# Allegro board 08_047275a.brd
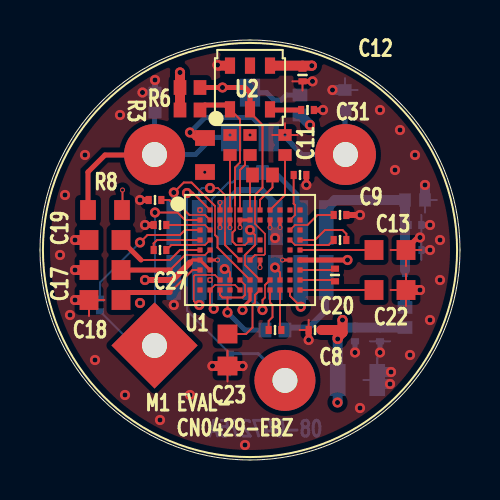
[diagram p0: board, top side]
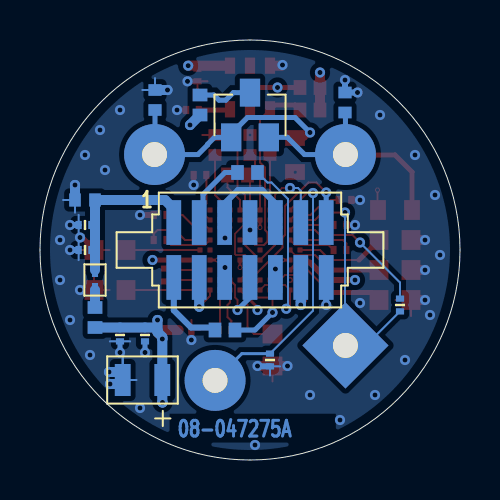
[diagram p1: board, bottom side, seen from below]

Outline 21 x 21 mm; copper layers: TOP, LAYER2, LAYER3, BOTTOM. Coordinates in mm from the lower left corner of the outline.
Outline path: 0,10.5 arc(3.08,17.92) 10.5,21 arc(17.92,17.92) 21,10.5 arc(17.92,3.08) 10.5,0 arc(3.08,3.08) 0,10.5

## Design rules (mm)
constraint set DEFAULT: min track width 0.1

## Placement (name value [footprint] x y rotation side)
C1  0.1uF  [C0201]  3 7.75 270 bottom
C2  0.1uF  [C0201]  9.5 5 270 bottom
C3  30PF  [C0402]  15.25 18 90 bottom
C4  30PF  [C0402]  5.75 17.88 270 bottom
C6  4.7uF  [C0402]  9.5 15.75 270 top
C7  4.7uF  [CPL0805]  15.88 4 0 bottom
C8  0.1uF  [C0201]  13.75 6.5 0 top
C9  0.1uF  [C0201]  15 12.25 180 top
C10  0.1uF  [C0201]  13 14.25 180 top
C11  4.7uF  [C0402]  12.25 15.75 270 top
C12  0.1uF  [C0201]  13.12 19.25 90 top
C13  0.47uF  [C0603]  17.5 10.5 0 top
C14  4.7uF  [C0402]  10.5 15.75 270 top
C15  0.1uF  [C0201]  6 11.75 0 top
C16  0.1uF  [C0201]  5.75 13 0 top
C17  0.47uF  [C0603]  3.25 9.5 180 top
C18  0.47uF  [C0603]  3.25 8 180 top
C19  0.47uF  [C0603]  3.25 11 180 top
C20  0.1uF  [C0201]  14.75 9.25 270 top
C21  0.1uF  [C0201]  11.75 6.5 180 top
C22  0.47uF  [C0603]  17.5 8.5 180 top
C23  0.47uF  [C0603]  9.38 5.5 90 top
C24  4.7UF  [C0402]  18.75 13 0 bottom
C25  0.1uF  [C0201]  18.75 11.75 0 bottom
C26  0.1uF  [C0201]  15.75 6.25 90 bottom
C27  0.1uF  [C0201]  6 10.5 180 top
C28  0.1uF  [C0201]  15 11 0 top
C29  1000PF  [C0201]  18.75 10.5 180 bottom
C30  1000PF  [C0201]  17 6.25 90 bottom
C31  0.1uF  [C0201]  13.38 17.5 180 top
E2  600OHM AT 100MEGHZ  [L0201H13]  18.25 9 270 bottom
M1  CO-A4  [MCO-A4_SKTLD98]  10.5 10.5 45 top
NOREF  -  []  5.75 6 0 top
NOREF#2  -  []  -124.5 -119.5 0 top
NOREF#3  -  []  5.5 15.5 0 top
NOREF#4  -  []  15.25 15.75 0 top
NOREF#5  -  []  -124.5 -119.5 0 top
NOREF#6  -  []  7.67 14.62 0 top
NOREF#7  -  []  9.75 -12.75 0 top
NOREF#8  -  []  18.18 3.34 0 top
NOREF#9  -  []  12.5 4 0 top
P1  SFM-107-02-L-D  [CNSAMTECSFM-107-02-X-D]  10.5 10.5 180 bottom
Q1  MMBFJ177  [SOT23]  10.5 17.25 180 bottom
R1  100  [R0402]  10.62 14.38 0 bottom
R2  100  [R0402]  11.75 6.5 180 bottom
R3  2.2K  [R0402]  7.5 17.5 0 top
R4  200  [R0402]  11.12 14.25 180 top
R5  100K  [R0402]  13 17.75 90 bottom
R6  2.2K  [R0402]  7.5 18.62 0 top
R7  0  [R0603]  8.25 15.25 270 top
R8  0  [R0603]  3.25 12.5 0 top
R11  1.6  [R0402]  18.25 7.12 270 bottom
U1  ADUCM355  [LGA72_5X6]  10.5 10.5 270 top
U2  MVH3002D  [LGA6H35]  10.5 18.62 0 top

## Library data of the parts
C1 C2 C8-C10 C12 C15 C16 C20 C21 C25-C28 C31 = CAP: Tolerance: 10; User Part Number: UPN; alternate symbols: (); part number: CAP_SM-0.1UF,6.3V,10,E011567,C0201; tolerance: 10
C3 C4 = CAP: User Part Number: UPN; Tolerance: 1; alternate symbols: (); part number: CAP_SM-30PF,50V,1,E023309,C0402; tolerance: 1
C6 C11 C14 = CAP: User Part Number: UPN; Tolerance: 10; alternate symbols: (); part number: CAP_SM-4.7UF,6.3V,10,E020089,C0402; tolerance: 10
C7 = CAPP: Tolerance: N/A; User Part Number: UPN; alternate symbols: (); part number: CAPP_SM-4.7UF,N/A,N/A,E020900,CPL0805; tolerance: N/A
C13 C17-C19 C22 C23 = CAP: User Part Number: UPN; Tolerance: 10; alternate symbols: (); part number: CAP_SM-0.47UF,25V,10,E010966,C0603; tolerance: 10
C24 = CAP: User Part Number: UPN; Tolerance: 20; alternate symbols: (); part number: CAP_SM-4.7UF,6.3V,20,E025260,C0402; tolerance: 20
C29 C30 = CAP: Tolerance: 5; User Part Number: UPN; alternate symbols: (); part number: CAP_SM-1000PF,25V,5,E028646,C0201; tolerance: 5
E2 = FERRITE: Tolerance: 25; User Part Number: UPN; alternate symbols: (); part number: FERRITE_SM-600OHM AT 100MEGHZ,25,E024592,L0201H13; tolerance: 25
M1 = MOD_CO_XX_V2: User Part Number: UPN; Tolerance: N/A; alternate symbols: (); part number: MOD_CO_XX_V2_TH-CO-A4,E025025,MCO-A4_SKTLD98; tolerance: N/A
P1 = CN14P_ODD_EVEN: User Part Number: UPN; Tolerance: N/A; alternate symbols: (); part number: CN14P_ODD_EVEN_SM-SFM-107-02-L-D,E029706,CNSAMTECSFM-107-02-X-D; tolerance: N/A
Q1 = TRANPJFET: User Part Number: UPN; Tolerance: N/A; alternate symbols: (); part number: TRANPJFET_SM-MMBFJ177,E020441,SOT23; tolerance: N/A
R1 R2 = RES: User Part Number: UPN; Tolerance: 1; alternate symbols: (R0402L); part number: RES_SM-100,E016329,1/10W,1,R0402; tolerance: 1
R3 R6 = RES: User Part Number: UPN; Tolerance: 5; alternate symbols: (R0402L); part number: RES_SM-2.2K,E003446,1/16W,5,R0402; tolerance: 5
R4 = RES: User Part Number: UPN; Tolerance: 0.1; alternate symbols: (R0402L); part number: RES_SM-200,E006431,1/16W,0.1,R0402; tolerance: 0.1
R5 = RES: User Part Number: UPN; Tolerance: 1; alternate symbols: (R0402L); part number: RES_SM-100K,E017051,1/16W,1,R0402; tolerance: 1
R7 R8 = RES: User Part Number: UPN; Tolerance: 5; alternate symbols: (R0603L); part number: RES_SM-0,E006826,1/10W,5,R0603; tolerance: 5
R11 = RES: User Part Number: UPN; Tolerance: 1; alternate symbols: (R0402L); part number: RES_SM-1.6,E014755,1/16W,1,R0402; tolerance: 1
U1 = ADUCM355: User Part Number: UPN; Tolerance: N/A; alternate symbols: (SKTPLA-72LHC50A01); part number: ADUCM355_SM-ADUCM355,E028185,LGA72_5X6; tolerance: N/A
U2 = ICMVH300XD: User Part Number: UPN; Tolerance: N/A; alternate symbols: (); part number: ICMVH300XD_SM-MVH3002D,E029189,LGA6H35; tolerance: N/A

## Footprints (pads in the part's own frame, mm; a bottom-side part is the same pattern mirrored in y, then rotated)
C0201
  rect 0.305x0.406 smd: 1(-0.318,0) 2(0.318,0)
C0402
  rect 0.584x0.66 smd: 1(-0.5,0) 2(0.5,0)
C0603
  rect 0.94x0.991 smd: 1(-0.8,0) 2(0.8,0)
CNSAMTECSFM-107-02-X-D
  rect 0.737x2.235 smd: 1(-3.81,1.372) 2(-3.81,-1.372) 3(-2.54,1.372) 4(-2.54,-1.372) 5(-1.27,1.372) 6(-1.27,-1.372) 7(0,1.372) 8(0,-1.372) 9(1.27,1.372) 10(1.27,-1.372) 11(2.54,1.372) 12(2.54,-1.372) 13(3.81,1.372) 14(3.81,-1.372)
CPL0805
  rect 0.787x1.6 smd: N(0.991,0) P(-0.991,0)
L0201H13
  rect 0.254x0.305 smd: 1(-0.277,0) 2(0.277,0)
LGA6H35
  rect 0.508x0.813 smd: 1(-1,-1.091) 2(0,-1.091) 3(1,-1.091) 4(1,1.091) 5(0,1.091) 6(-1,1.091)
LGA72_5X6
  rect 0.254x0.254 smd: A1(-2,-2.5) A2(-2,-2) A3(-2,-1.5) A4(-2,-1) A5(-2,-0.5) A6(-2,0) A7(-2,0.5) A8(-2,1) A9(-2,1.5) A10(-2,2) A11(-2,2.5) B1(-1.5,-2.5) B2(-1.5,-2) B3(-1.5,-1.5) B4(-1.5,-1) B5(-1.5,-0.5) B6(-1.5,0) B7(-1.5,0.5) B8(-1.5,1) B9(-1.5,1.5) B10(-1.5,2) B11(-1.5,2.5) C1(-1,-2.5) C2(-1,-2) C10(-1,2) C11(-1,2.5) D1(-0.5,-2.5) D2(-0.5,-2) D5(-0.5,-0.5) D6(-0.5,0) D7(-0.5,0.5) D10(-0.5,2) D11(-0.5,2.5) E1(0,-2.5) E2(0,-2) E5(0,-0.5) E7(0,0.5) E10(0,2) E11(0,2.5) F1(0.5,-2.5) F2(0.5,-2) F5(0.5,-0.5) F6(0.5,0) F7(0.5,0.5) F10(0.5,2) F11(0.5,2.5) G1(1,-2.5) G2(1,-2) G10(1,2) G11(1,2.5) H1(1.5,-2.5) H2(1.5,-2) H3(1.5,-1.5) H4(1.5,-1) H5(1.5,-0.5) H6(1.5,0) H7(1.5,0.5) H8(1.5,1) H9(1.5,1.5) H10(1.5,2) H11(1.5,2.5) J1(2,-2.5) J2(2,-2) J3(2,-1.5) J4(2,-1) J5(2,-0.5) J6(2,0) J7(2,0.5) J8(2,1) J9(2,1.5) J10(2,2) J11(2,2.5)
MCO-A4_SKTLD98
  rect 3.048x3.048 hole 1.25: 1(-6.75,0)
  round 3.048 hole 1.25: 2(0,6.75) 3(6.75,0) 4(-3.375,-5.846)
R0402
  rect 0.635x0.737 smd: 1(-0.5,0) 2(0.5,0)
R0603
  rect 0.787x0.991 smd: 1(-0.85,0) 2(0.85,0)
SOT23
  rect 1.016x1.397 smd: 1(-0.94,-1.118) 2(0.94,-1.118) 3(0,1.118)

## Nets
DGND: C2.2(N2) C3.2(N2) C4.1 C6.1 C7.N(N2) C8.1 C9.1 C10.1 C11.1 C12.1 C13.2(N2) C14.1 C15.1 C16.1 C17.2(N2) C18.2(N2) C19.2(N2) C22.1 C23.1 C24.2(N2) C25.2(N2) C26.1 C29.1 C30.1 C31.1 P1.5 P1.9 P1.14(N7) U1.B3 U1.B4 U1.B5 U1.B6 U1.B8 U1.B9 U1.F2 U1.F7 U1.F10 U1.H2 U2.6(VSS)
VBAT: C24.1 C25.1 C29.2(N2) E2.1 P1.1
VDD: C7.P C8.2(N2) C12.2(N2) C26.2(N2) C30.2(N2) R3.1 R5.1 R6.1 R11.2(N2) U1.F1 U1.F11 U1.G2 U1.J6 U2.4
BB_SCL/CS0: R3.2(N2) U1.D6 U2.1
BB_SDA/MISO: R6.2(N2) U1.F6 U2.2
CAP_POT0: C1.1 U1.C1
CE0: C1.2(N2) M1.1 U1.B1
DE0: C2.1 M1.4 U1.A2
EXT_INT: P1.11 U1.F5
LPF0: C6.2(N2) U1.A4
LPF1: C11.2(N2) U1.A8
RC0_0: C27.2(N2) U1.D1
RC0_1: C27.1 U1.D2
RC1_0: C28.2(N2) U1.D11
RC1_1: C28.1 U1.D10
RE0: C3.1 M1.3 Q1.1 R7.1
RESET: P1.4 U1.J10
SCL/UART_RX: R1.1 U1.J2 U1.J5
SDA/UART_TX: R2.2(N2) U1.H5 U1.J3
SE0: C4.2(N2) M1.2(WE) Q1.2(S) R8.1
SPI0_CLK: P1.6 U1.H9
SPI0_CS0: P1.13 U1.H6
SPI0_MISO: P1.7 U1.H7
SPI0_MOSI: P1.8 U1.H8
SWCLK: P1.12 U1.H3
SWDIO: P1.10 U1.H4
UNNAMED_4_ADUCM355_I48_ADCVBIAS: C13.1 U1.E11
UNNAMED_4_ADUCM355_I48_AVDDREG: C19.1 U1.E1
UNNAMED_4_ADUCM355_I48_DVDDREG: C23.2(N2) U1.J7
UNNAMED_4_ADUCM355_I48_DVDDREGA: C18.1 U1.G1
UNNAMED_4_ADUCM355_I48_RCAL0: R4.1 U1.A7
UNNAMED_4_ADUCM355_I48_RCAL1: R4.2(N2) U1.A6
UNNAMED_4_ADUCM355_I48_RE0: R7.2(N2) U1.A1
UNNAMED_4_ADUCM355_I48_SE0: R8.2(N2) U1.A3
UNNAMED_4_ADUCM355_I48_VBIAS0: C15.2(N2) U1.C2
UNNAMED_4_ADUCM355_I48_VBIAS1: C9.2(N2) U1.C10
UNNAMED_4_ADUCM355_I48_VCDCCAP2: C20.1 U1.G11
UNNAMED_4_ADUCM355_I48_VDCDCC_1: C21.1 U1.J9
UNNAMED_4_ADUCM355_I48_VDCDCC_2: C20.2(N2) U1.H11
UNNAMED_4_ADUCM355_I48_VDCDCC_3: C22.2(N2) U1.J11
UNNAMED_4_ADUCM355_I48_VDCDCCAP: C21.2(N2) U1.J8
UNNAMED_4_ADUCM355_I48_VREF1: C14.2(N2) U1.A5
UNNAMED_4_ADUCM355_I48_VREF2: C17.1 U1.E2
UNNAMED_4_ADUCM355_I48_VZERO0: C16.2(N2) U1.B2
UNNAMED_4_ADUCM355_I48_VZERO1: C10.2(N2) U1.B10
UNNAMED_4_CAP_I187_N2: C31.2(N2) U2.3
UNNAMED_4_CN14PODDEVEN_I182_N2: P1.3 R1.2(N2)
UNNAMED_4_CN14PODDEVEN_I199_N1: P1.2 R2.1
UNNAMED_4_FERRITE_I82_N2: E2.2(N2) R11.1
UNNAMED_4_RES_I195_N2: Q1.3 R5.2(N2)

Pads without a net: U1 A9 A10 A11 B7 B11 C11 D5 D7 E5 E7 E10 G10 H1 H10 J1 J4; U2 5

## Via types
v1: diameter 0.254, hole 0.152, TOP to LAYER2, 16 vias
v2: diameter 0.508, hole 0.254, TOP to BOTTOM, 71 vias

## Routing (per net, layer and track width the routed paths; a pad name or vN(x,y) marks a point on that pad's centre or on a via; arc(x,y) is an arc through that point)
DGND: length 49.2
  TOP w0.1: 11.62,16.25 v1(12.25,16.25) ; v1(12.25,16.25) 12.88,16.25 ; v1(12.25,16.25) 12.25,16.84 ; C13.2 19.07,10.5 ; C13.2 17.53,10.5 ; C13.2 18.3,9.7 ; 2.45,7.2 C18.2 3.22,8 ; 9.38,5.47 C23.1 9.38,3.93 ; 13.12,18.48 C12.1 12.62,18.93 ; 12.98,6.5 C8.1 13.43,7 ; C22.1 18.3,9.3 ; C22.1 17.53,8.5 ; C22.1 18.3,7.7
  TOP w0.15: U1.F10 v1(12.12,10) ; v1(10,11.62) 10,11.95 10.05,12 ; U1.B8 v1(11.5,11.62) ; U1.B3 v1(9,11.62) ; U1.F7 v1(11,9.62) ; 10.05,12 U1.B6 ; 10.05,12 U1.B5 ; U1.B4 v1(9.5,11.62) ; U1.B9 v1(12,11.62) ; U1.F2 v1(8.88,10)
  TOP w0.25: C12.1 v2(13.62,18.93) ; C13.2 18.3,10.55 18.88,11.12 v2(19,11.12) ; C31.1 v2(14.15,17.5) ; v2(13.32,13.75) C10.1
  TOP w0.3: C9.1 v2(16,12.25) ; C16.1 v2(5,13) ; C8.1 v2(13.43,6) ; C15.1 v2(5.25,11.75)
  TOP w0.5: v2(8.88,19.75) 8.91,19.72 U2.6 ; v2(10.12,4.7) C23.1 v2(8.62,4.7) ; C18.2 v2(1.75,8) ; C22.1 v2(19,8.5) ; C17.2 v2(1.75,9.5) ; C19.2 v2(1.75,11)
  BOTTOM w0.1: 9.5,4.23 C2.2 9,4.68 ; 16.86,4.4 16.86,5.09 16.87,5.1 C7.N ; 19.25,12.37 C24.2 19.84,13 ; C7.N 17.56,4 ; C7.N 16.17,4 ; 16.5,5.93 C30.1 17.5,5.93 ; 15.88,18.5 C3.2 15.25,19.09 ; 19.07,12.25 C25.2 19.07,11.25 ; 19.07,10 C29.1 19.07,11
  BOTTOM w0.25: C26.1 v2(15.75,5.38) ; C30.1 v2(17,5.38)
  BOTTOM w0.3: C2.2 10.11,4.68 v2(10.12,4.7) ; P1.9 9.23,12.83 9.9,13.5 11.1,13.5 11.75,12.85 v2(11.75,11.1) 11.77,11.12 P1.5 ; C25.2 v2(19.5,11.75) ; P1.14 v2(6.69,7.75) ; v2(5.75,19) C4.1 v2(5.12,18.38) ; C29.1 v2(19.5,10.5)
  BOTTOM w0.5: C24.2 v2(19.25,13.75) ; v2(17.55,4.4) 16.86,4.4 16.86,4.01 C7.N 16.87,3.85 16.92,3.8 v2(17.5,3.8) ; C3.2 v2(14.62,18.5)
  vias: v1(8.5,9) v1(9.5,16.25) v1(10.5,16.25) v2(1,10.25) v2(1.25,13.25) v2(1.5,7.25) v2(2.25,15.25) v2(2.75,5) v2(4,17.25) v2(4.25,3.25) v2(5,7.85) v2(6,2) v2(7.5,3.25) v2(10.25,0.75) v2(16,2.6) v2(17,17.5) v2(17.75,14.5) v2(18,16.5) v2(18.5,5.25) v2(18.75,15.25) v2(19.5,7) v2(20,11) v2(20,9)
VBAT: length 8.9
  BOTTOM w0.25: 18.25,9.5 18.25,9.28 ; C25.1 18.25,11.75 ; C29.2 18.25,10.5
  BOTTOM w0.5: 18.25,9.5 C24.1 14.75,13 14.31,12.56 P1.1
VDD: length 21.9
  TOP w0.15: U1.J6 10.5,8 10.12,7.62 v2(10.12,7.5) ; 7.5,9.88 7.62,10 U1.F1 U1.G2
  TOP w0.25: C12.2 13.12,19.72 ; U1.F11 v2(15.38,10)
  TOP w0.3: v2(5.25,9) 6.62,9 7.5,9.88
  TOP w0.5: 15.12,6.38 15,6.5 C8.2 ; 15.12,6.38 14.88,6.13 v2(14.88,6.05) ; 15.12,6.38 v2(15.12,7) ; v2(13.59,19.72) U2.4 ; v2(7,19.38) R6.1 R3.1
  BOTTOM w0.25: 15.75,6.62 C26.2 ; C30.2 17,6.62
  BOTTOM w0.5: R11.2 15.25,6.62 15.12,6.5 ; 15.12,6.5 v2(15.12,7) ; 15.12,6.5 15.12,6.39 14.88,6.15 v2(14.88,6.05) C7.P 14.88,2.88 v2(14.88,2.88) ; R5.1 v2(13.5,16.75)
BB_SCL/CS0: length 9.7
  TOP w0.08: U1.D6 10.25,10.75 9.8,10.75 ; 9.75,11.5 9.75,12.75
  TOP w0.1: U2.1 10,17.03 10,14.88 9.75,14.62 9.75,12.75 ; 9.8,10.75 9.62,10.93 9.62,11.38 9.75,11.5
  TOP w0.25: U2.1 9.28,17.75 8.25,17.75 R3.2
BB_SDA/MISO: length 12.2
  TOP w0.08: 10.75,10.25 11.2,10.25 11.25,10.3 11.25,11.31 10.75,11.81 10.75,12.75
  TOP w0.1: U2.2 10.5,17.38 11.12,16.75 11.12,13.62 10.75,13.25 10.75,12.75 ; U1.F6 10.75,10.25
  TOP w0.25: U2.2 10.5,18.38 10.25,18.62 v2(9.12,18.62) R6.2
CAP_POT0: length 6.9
  TOP w0.1: v2(5,10.88) 5.38,11.25 7,11.25 7.25,11.5 U1.C1
  BOTTOM w0.1: v2(5,10.88) 3,8.88 C1.1
CE0: length 12.5
  TOP w0.1: v2(5.75,12.38) 6.88,12.38 7.25,12 U1.B1
  BOTTOM w0.1: v2(5.75,12.38) 5.75,5.75 M1.1 4.71,5.73 C1.2
DE0: length 13.7
  TOP w0.1: v2(7.35,13.35) 7.38,13.38 7.62,13.38 U1.A2
  BOTTOM w0.1: v2(7.35,13.35) 7.35,7.47 C2.1
  BOTTOM w0.15: C2.1 10.91,5.32 12.25,3.98
EXT_INT: length 6.6
  TOP w0.08: v2(8.5,13.6) 8.9,13.6 9.25,13.25 9.25,11.38
  TOP w0.1: U1.F5 9.25,10.75 9.25,11.38
  BOTTOM w0.1: v2(8.5,13.6) 8.1,13.6 7.96,13.46 P1.11
LPF0: length 2.8
  TOP w0.1: U1.A4 C6.2
LPF1: length 3.1
  TOP w0.1: U1.A8 12.25,13.25 C11.2
RC0_0: length 2.7
  TOP w0.1: U1.D1 5.85,11 5.68,10.83 C27.2
RC0_1: length 2.4
  TOP w0.08: U1.D2 8.25,10.75 7.75,10.75
  TOP w0.1: 7.75,10.75 6.57,10.75 C27.1
RC1_0: length 2.9
  TOP w0.1: C28.2 15.32,11.31 15.12,11.5 14.25,11.5 13.75,11 U1.D11
RC1_1: length 2.4
  TOP w0.08: U1.D10 12.75,10.75 13.38,10.75
  TOP w0.1: 13.38,10.75 14.43,10.75 C28.1
RE0: length 12.1
  TOP w0.25: R7.1 7.78,16.1 v2(7.5,16.38)
  BOTTOM w0.25: v2(7.5,16.38) 8.25,17.12 10.62,17.12 11.44,16.31 Q1.1 12.27,16.13 12.62,15.79 12.62,15.76 13.1,15.27 M1.3 15.25,15.3 C3.1
RESET: length 2.5
  TOP w0.1: U1.J10 12.5,8.21 v2(13.04,7.67)
  BOTTOM w0.5: P1.4 v2(13.04,7.67)
SCL/UART_RX: length 10.3
  TOP w0.08: U1.J5 9.75,8.75 8.75,8.75 U1.J2
  TOP w0.1: v2(8.69,7.56) 8.5,7.75 U1.J2
  BOTTOM w0.1: v2(8.69,7.56) 8.6,7.65 8.6,13.05 9.43,13.88 9.62,13.88 R1.1
SDA/UART_TX: length 5.4
  TOP w0.08: U1.H5 10.25,8.75 10.25,8.25
  TOP w0.1: 9.38,8.12 9.12,8.12 9,8.25 U1.J3 ; 9.38,8.12 10.12,8.12 10.25,8.25 ; 9.38,8.12 v2(9.38,7.38)
  BOTTOM w0.25: R2.2 10.25,6.5 v2(9.38,7.38)
SE0: length 11.9
  TOP w0.25: R8.1 2.4,14.4 3.25,15.25 5.7,15.25 M1.2
  BOTTOM w0.25: C4.2 5.73,17.35 M1.2 7.77,15.27 8.63,16.13 Q1.2
SPI0_CLK: length 0.7
  TOP w0.1: U1.H9 12,9.38 v2(11.75,9.62)
SPI0_CS0: length 8.7
  TOP w0.08: 8.75,12.7 8.75,11.25
  TOP w0.1: U1.H6 8.88,10.62 8.88,11.12 8.75,11.25 ; v2(6.69,13.38) 7.19,13.88 7.58,13.88 8.75,12.7
  BOTTOM w0.25: v2(6.69,13.38) P1.13
SPI0_MISO: length 3.5
  TOP w0.08: 10.25,9.75 10.25,10.25 ; 10.75,10.75 10.75,11.25
  TOP w0.1: U1.H7 10.25,9.75 ; 10.25,10.25 10.75,10.75 ; 10.75,11.25 v2(10.5,11.5)
  BOTTOM w0.1: P1.7 v2(10.5,11.5)
SPI0_MOSI: length 3.5
  TOP w0.08: 11.25,8.75 11.25,8.12
  TOP w0.1: v2(11.12,7.5) 11.12,8 11.25,8.12 ; U1.H8 11.25,8.75
  BOTTOM w0.25: v2(11.12,7.5) 10.5,8.12 P1.8
SWCLK: length 4.4
  TOP w0.08: v2(7.96,7.75) 7.88,7.75 7.69,7.94 7.69,9.19 7.75,9.25 8.75,9.25 U1.H3
  BOTTOM w0.5: P1.12 7.96,7.92 7.96,7.91 v2(7.96,7.75)
SWDIO: length 1.2
  TOP w0.1: v2(9.23,9.55) 9.23,9.5 9.28,9.45 9.43,9.45 9.5,9.38 U1.H4
  BOTTOM w0.25: v2(9.23,9.55) P1.10
UNNAMED_4_ADUCM355_I48_ADCVBIAS: length 3.7
  TOP w0.1: U1.E11 C13.1
UNNAMED_4_ADUCM355_I48_AVDDREG: length 4.6
  TOP w0.1: 5.05,10 6.5,10 7,10.5 U1.E1
  TOP w0.25: C19.1 5.05,10
UNNAMED_4_ADUCM355_I48_DVDDREG: length 3.4
  TOP w0.1: U1.J7 10.75,8.25 10.75,7.88 10.62,7.75 10.62,6.62 10.3,6.3 C23.2
UNNAMED_4_ADUCM355_I48_DVDDREGA: length 4.6
  TOP w0.1: U1.G1 7.62,9.5 6.5,8.38
  TOP w0.25: C18.1 4.42,8.38 6.5,8.38
UNNAMED_4_ADUCM355_I48_RCAL0: length 2
  TOP w0.1: U1.A7 11,13.01 11.62,13.63 R4.1
UNNAMED_4_ADUCM355_I48_RCAL1: length 1.8
  TOP w0.1: U1.A6 10.5,14.12 R4.2
UNNAMED_4_ADUCM355_I48_RE0: length 2
  TOP w0.3: R7.2 v1(8.24,14.39)
  LAYER2 w0.1: v1(8,12.5) 8,14.15 v1(8.24,14.39)
UNNAMED_4_ADUCM355_I48_SE0: length 7.1
  TOP w0.1: R8.2 4.12,12.53 v1(4.12,13.5) ; U1.A3 v1(9,12.88)
  LAYER2 w0.1: v1(4.12,13.5) 5.75,13.5 7.12,12.12 8.25,12.12 v1(9,12.88)
UNNAMED_4_ADUCM355_I48_VBIAS0: length 2.3
  TOP w0.08: U1.C2 8.25,11.75 7.75,11.75
  TOP w0.1: C15.2 7.75,11.75
UNNAMED_4_ADUCM355_I48_VBIAS1: length 2.5
  TOP w0.08: 13.38,11.75 12.75,11.75 U1.C10
  TOP w0.1: C9.2 13.88,12.25 13.38,11.75
UNNAMED_4_ADUCM355_I48_VCDCCAP2: length 1.8
  TOP w0.1: U1.G11 14.68,9.5 C20.1
UNNAMED_4_ADUCM355_I48_VDCDCC_1: length 2
  TOP w0.1: U1.J9 12,6.57 C21.1
UNNAMED_4_ADUCM355_I48_VDCDCC_2: length 1.8
  TOP w0.1: U1.H11 14.68,9 C20.2
UNNAMED_4_ADUCM355_I48_VDCDCC_3: length 3.7
  TOP w0.1: U1.J11 C22.2
UNNAMED_4_ADUCM355_I48_VDCDCCAP: length 2.1
  TOP w0.1: C21.2 11.43,6.95 11.62,7.15 11.62,7.75 11.5,7.88 U1.J8
UNNAMED_4_ADUCM355_I48_VREF1: length 3.1
  TOP w0.1: C14.2 10.3,15.25 10.25,15.2 10.25,14.75 10,14.5 U1.A5
UNNAMED_4_ADUCM355_I48_VREF2: length 4.9
  TOP w0.08: U1.E2 8.25,10.25 7.25,10.25
  TOP w0.1: 6.5,9.5 7.25,10.25
  TOP w0.25: C17.1 6.5,9.5
UNNAMED_4_ADUCM355_I48_VZERO0: length 2.8
  TOP w0.08: 7.47,12.25 8.25,12.25
  TOP w0.1: C16.2 6.47,13 6.82,12.65 7.07,12.65 7.47,12.25 ; 8.25,12.25 U1.B2
UNNAMED_4_ADUCM355_I48_VZERO1: length 2.4
  TOP w0.08: U1.B10 12.75,12.25 12.75,12.75
  TOP w0.1: C10.2 12.68,12.82 12.75,12.75
UNNAMED_4_CAP_I187_N2: length 1.6
  TOP w0.25: U2.3 11.53,17.5 C31.2
UNNAMED_4_CN14PODDEVEN_I182_N2: length 3.7
  BOTTOM w0.25: R1.2 11.75,14.38 12.85,13.28 12.85,12.06 P1.3
UNNAMED_4_CN14PODDEVEN_I199_N1: length 4.1
  BOTTOM w0.3: P1.2 14.31,7.49 13.45,6.62 12.38,6.62 R2.1
UNNAMED_4_FERRITE_I82_N2: length 1.1
  BOTTOM w0.25: 18.25,8.5 18.25,8.72
  BOTTOM w0.5: R11.1 18.25,8.5
UNNAMED_4_RES_I195_N2: length 2.8
  BOTTOM w0.25: R5.2 12.31,18.25 12.05,17.99 11.71,17.99 11.33,18.37 Q1.3

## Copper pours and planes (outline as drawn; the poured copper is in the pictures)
DGND on TOP: 10.5,0.5 0.5,10.5 3.43,17.57 10.5,20.5 17.57,17.57 20.5,10.5 ; 2 cut-outs
DGND on BOTTOM: 10.5,0.5 0.5,10.5 3.43,17.57 10.5,20.5 17.57,17.57 20.5,10.5 ; 2 cut-outs
DGND on LAYER2: 10.5,0.5 0.5,10.5 3.43,17.57 10.5,20.5 17.57,17.57 20.5,10.5
VDD on LAYER3: 10.5,0.5 0.5,10.5 3.43,17.57 10.5,20.5 17.57,17.57 20.5,10.5

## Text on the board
BOTTOM: 08-047275A
User.Comments: NOTE 1: INSERT MILMAX PIN RECEPTACLES AS INDICATED ABOVE. SEE M1 ON BOM. | SEE NOTE 1
Ref Des/Silkscreen Top: EVAL- | CN0429-EBZ
LAYER2: L2 Internal GND | 08-      -07
LAYER3: L3 Internal PWR | 08-      -08
XSECTION_CHART: Primary Side Silkscreen | Primary Side Soldermask | 0.035 (1oz) Copper Plating | Primary side 0.017 (0.5oz) Copper Foil | FR4 Prepreg | 0.035 (1oz) Copper | Secondary Side 0.017 (0.5oz) Copper Foil | FR4 CORE | Secondary Side Soldermask | Secondary side Silkscreen | 1.6mm +/-10% | 4 LAYER STACKUP
DIMENSION: Dia. 21mm
User.22: 10. Manufacturer UL and Date codes on the bottom side silkscreen | 1. Material: 4 Layer FR4 glass epoxy laminate 1.6mm +/- 10%. material to be RoHS compliant. | 2. Plated thru holes and conductive pattern electroplated with 0.255mm min. thick copper. | 3. Processing tolerence: | 4. Warp and twist within 0.1875mm per 25mm (0.75%) | 5. Dimensions are for the finished part. | 6. SOLDERMASK: liquid Photo Imeagable soldermask over bare copper (SMOBC), | 7. SCREENING: Screen component outlines and nomenclature using indelible white ink on both sides. | 8. Electrically test 100%. | 9. Break all sharp edges 0.35mm Radius max. | Board to be fabricated per IPC-6012A, CLASS 2. | Terminal areas and plated thru holes to be ENIG plated. | colour GREEN both sides using the pattern provided. No mask is permitted on the terminal areas. | Soldermask to etch registration within 0.125mm total. | A. Conductive pattern front to back registration within 0.125mm total. | B. Minimum annual ring surrounding holes 0.05mm. | C. Finished conductive pattern to be within 0.05mm of true size. | D. Minimumfeature size 0.2mm | E. Minimum air gap 0.12mm | Nomenclature shall be legible. Screen to etch registration within 0.15mm total. | FABRICATION NOTES: | 1 | FABRICATION | 09-047275-01 | A
